Omron CX-Programmer project NuevoProyecto (CX-Programmer 3.01)

# PLC NuevoPLC1: CPM2* 

## Global symbols (name address type ; comment)
DM200 CHANNEL  ; Cantidad de escl
DM201 CHANNEL  ; DM a partir de l
DM2010 CHANNEL  ; CRC del esclavo
DM2011 CHANNEL  ; CRC del esclavo
DM2012 CHANNEL  ; CRC del esclavo
DM2013 CHANNEL  ; CRCdel esclavo 4
DM2014 CHANNEL  ; CRC del esclavo
DM2015 CHANNEL  ; CRC del esclavo
DM2016 CHANNEL  ; CRC del esclavo
DM2017 CHANNEL  ; CRC del esclavo
DM2018 CHANNEL  ; CRC del esclavo
DM2019 CHANNEL  ; CRC del esclavo
DM202 CHANNEL  ; Timeout de cada
DM2020 CHANNEL  ; CRC del esclavo
DM2021 CHANNEL  ; CRC del esclavo
DM2022 CHANNEL  ; CRC del esclavo
DM2023 CHANNEL  ; CRC del esclavo
DM2024 CHANNEL  ; CRC del esclavo
DM2025 CHANNEL  ; CRC del esclavo
DM2026 CHANNEL  ; CRC del esclavo
DM2027 CHANNEL  ; CRC del esclavo
DM2028 CHANNEL  ; CRC del esclavo
DM2029 CHANNEL  ; CRC del esclavo
DM2030 CHANNEL  ; CRC del esclavo
DM2031 CHANNEL  ; CRC del esclavo
DM2032 CHANNEL  ; CRC del esclavo
DM2033 CHANNEL  ; CRC del esclavo
DM2034 CHANNEL  ; CRC del esclavo
DM2035 CHANNEL  ; CRC del esclavo
DM2036 CHANNEL  ; CRC del esclavo
DM2037 CHANNEL  ; CRC del esclavo
DM2038 CHANNEL  ; CRC del esclavo
DM2039 CHANNEL  ; CRC del esclavo
DM2040 CHANNEL  ; CRC del esclavo
DM2041 CHANNEL  ; CRC del esclavo

## Program NuevoPrograma1 (no task)

### Section Sección1

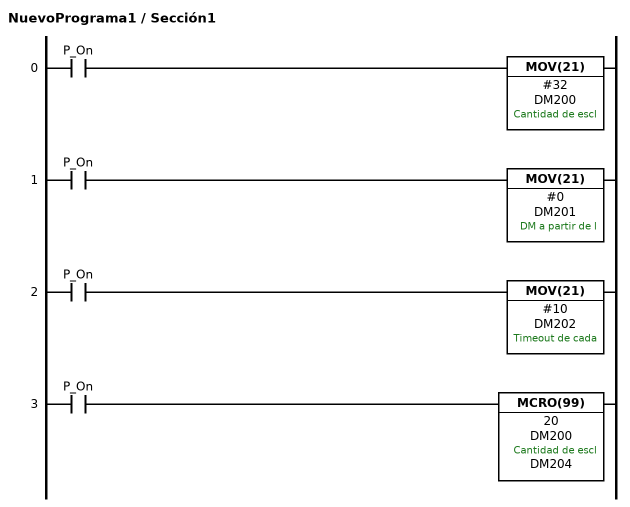
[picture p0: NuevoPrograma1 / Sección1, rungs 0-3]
; rung 0
LD P_On
MOV(21) #32 DM200  ; Cantidad de escl
; rung 1
LD P_On
MOV(21) #0 DM201  ; DM a partir de l
; rung 2
LD P_On
MOV(21) #10 DM202  ; Timeout de cada
; rung 3
LD P_On
MCRO(99) 20 DM200 DM204  ; Cantidad de escl

### Section Sección2

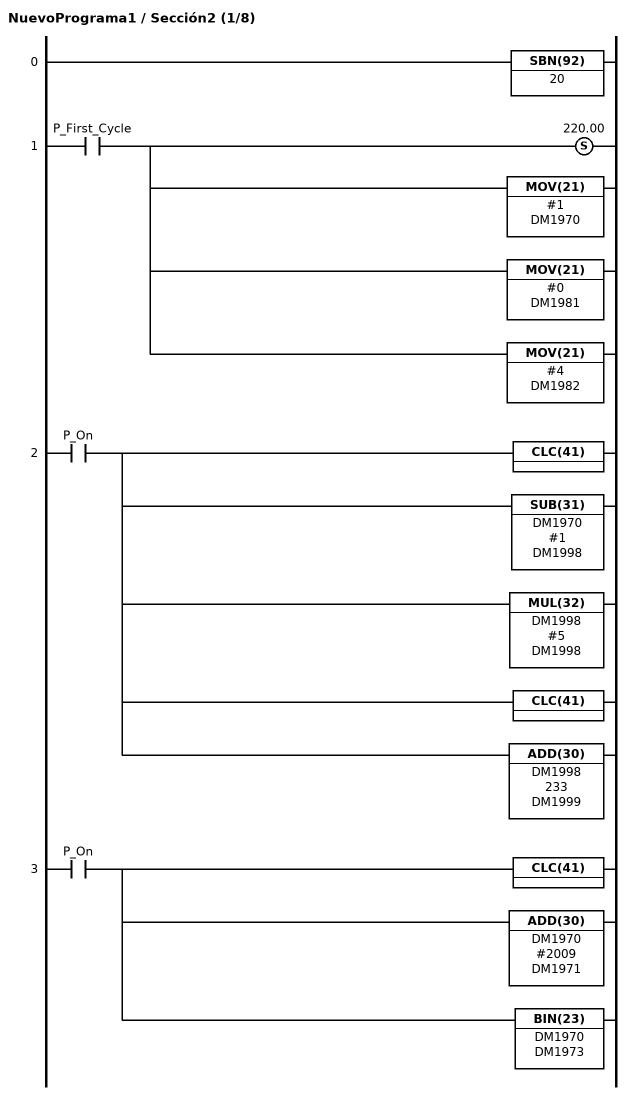
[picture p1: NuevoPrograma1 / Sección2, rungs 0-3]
; rung 0
SBN(92) 20
; rung 1
LD P_First_Cycle
SET 220.00
MOV(21) #1 DM1970
MOV(21) #0 DM1981
MOV(21) #4 DM1982
; rung 2
LD P_On
CLC(41)
SUB(31) DM1970 #1 DM1998
MUL(32) DM1998 #5 DM1998
CLC(41)
ADD(30) DM1998 233 DM1999
; rung 3
LD P_On
CLC(41)
ADD(30) DM1970 #2009 DM1971
BIN(23) DM1970 DM1973

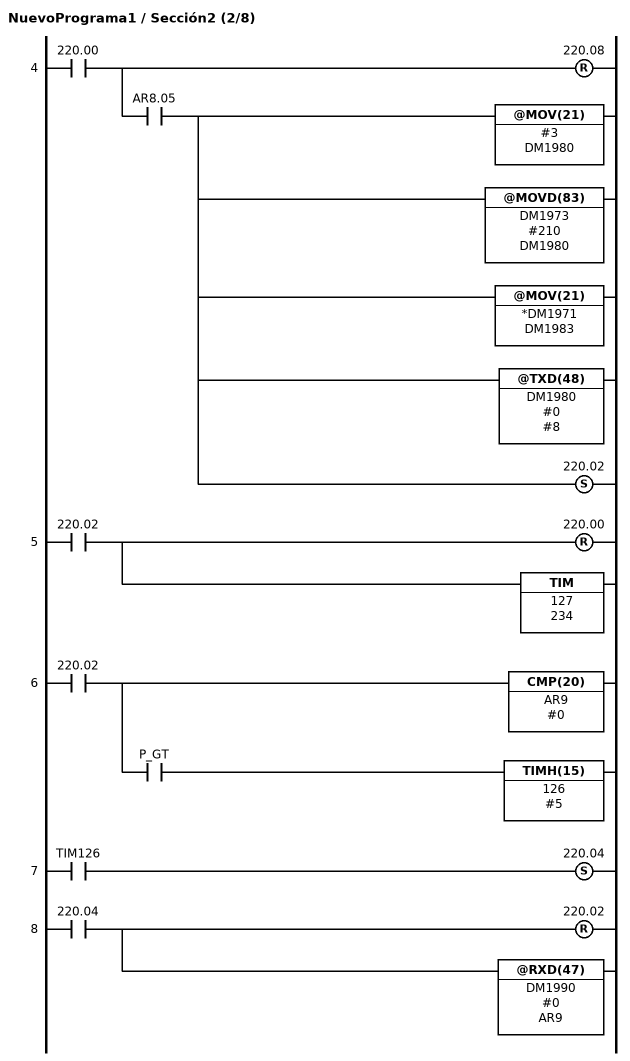
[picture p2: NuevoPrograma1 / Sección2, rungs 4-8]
; rung 4
LD 220.00
RSET 220.08
AND AR8.05
@MOV(21) #3 DM1980
@MOVD(83) DM1973 #210 DM1980
@MOV(21) *DM1971 DM1983
@TXD(48) DM1980 #0 #8
SET 220.02
; rung 5
LD 220.02
RSET 220.00
TIM 127 234
; rung 6
LD 220.02
CMP(20) AR9 #0
AND P_GT
TIMH(15) 126 #5
; rung 7
LD TIM126
SET 220.04
; rung 8
LD 220.04
RSET 220.02
@RXD(47) DM1990 #0 AR9

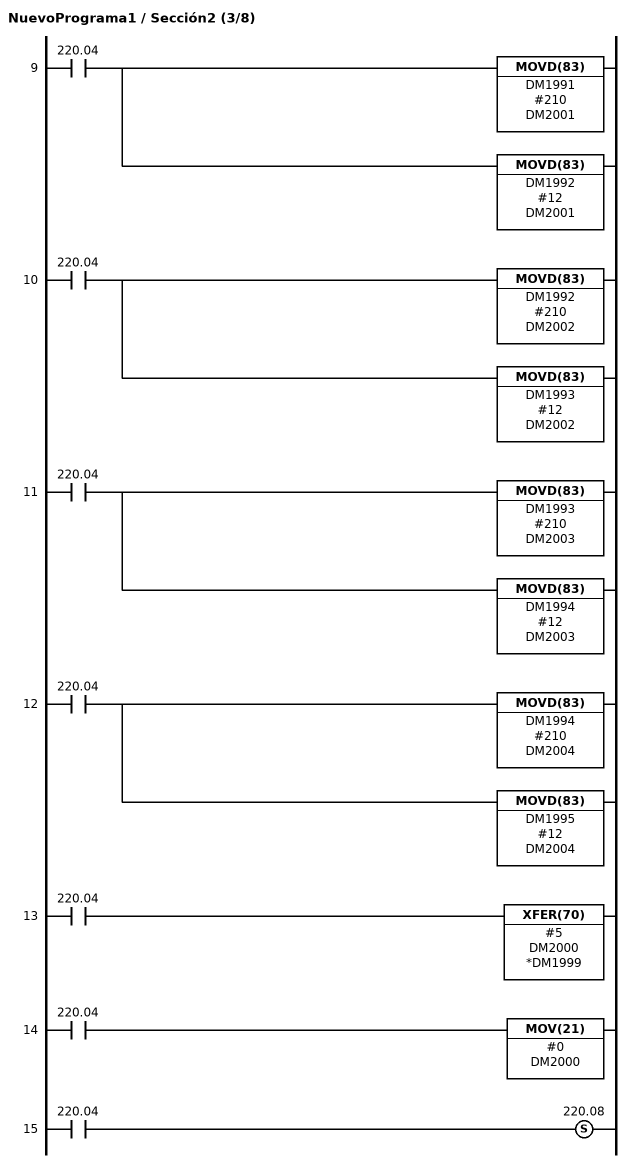
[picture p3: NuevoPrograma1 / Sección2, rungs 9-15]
; rung 9
LD 220.04
MOVD(83) DM1991 #210 DM2001
MOVD(83) DM1992 #12 DM2001
; rung 10
LD 220.04
MOVD(83) DM1992 #210 DM2002
MOVD(83) DM1993 #12 DM2002
; rung 11
LD 220.04
MOVD(83) DM1993 #210 DM2003
MOVD(83) DM1994 #12 DM2003
; rung 12
LD 220.04
MOVD(83) DM1994 #210 DM2004
MOVD(83) DM1995 #12 DM2004
; rung 13
LD 220.04
XFER(70) #5 DM2000 *DM1999
; rung 14
LD 220.04
MOV(21) #0 DM2000
; rung 15
LD 220.04
SET 220.08

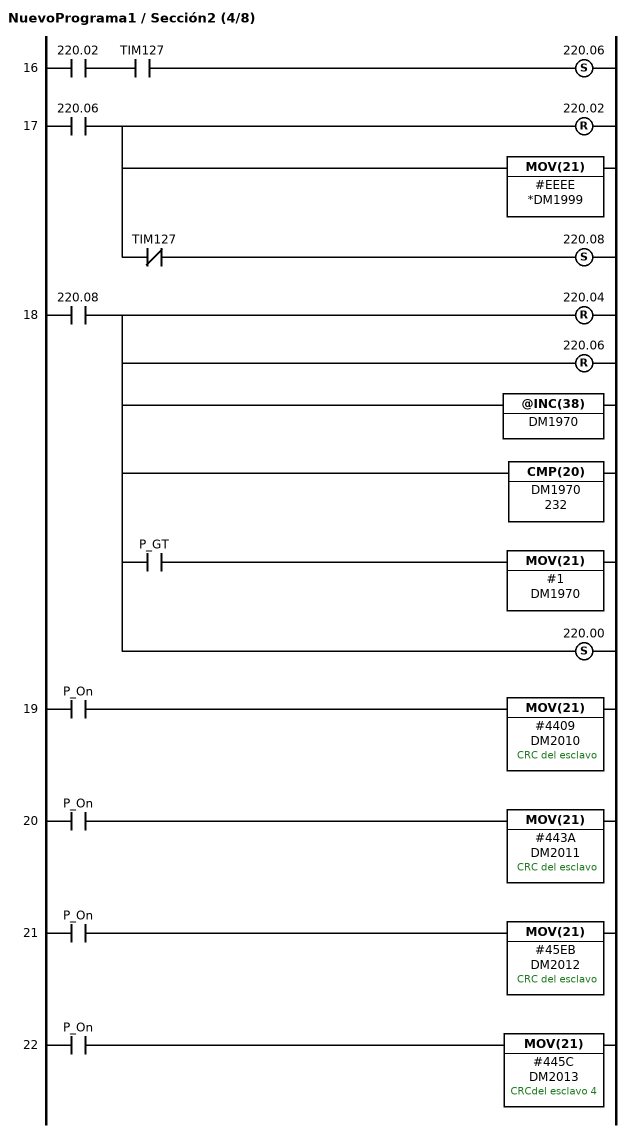
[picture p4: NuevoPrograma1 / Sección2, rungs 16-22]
; rung 16
LD 220.02
AND TIM127
SET 220.06
; rung 17
LD 220.06
RSET 220.02
MOV(21) #EEEE *DM1999
ANDNOT TIM127
SET 220.08
; rung 18
LD 220.08
OUT TR0
RSET 220.04
RSET 220.06
@INC(38) DM1970
CMP(20) DM1970 232
AND P_GT
MOV(21) #1 DM1970
LD TR0
SET 220.00
; rung 19
LD P_On
MOV(21) #4409 DM2010  ; CRC del esclavo
; rung 20
LD P_On
MOV(21) #443A DM2011  ; CRC del esclavo
; rung 21
LD P_On
MOV(21) #45EB DM2012  ; CRC del esclavo
; rung 22
LD P_On
MOV(21) #445C DM2013  ; CRCdel esclavo 4

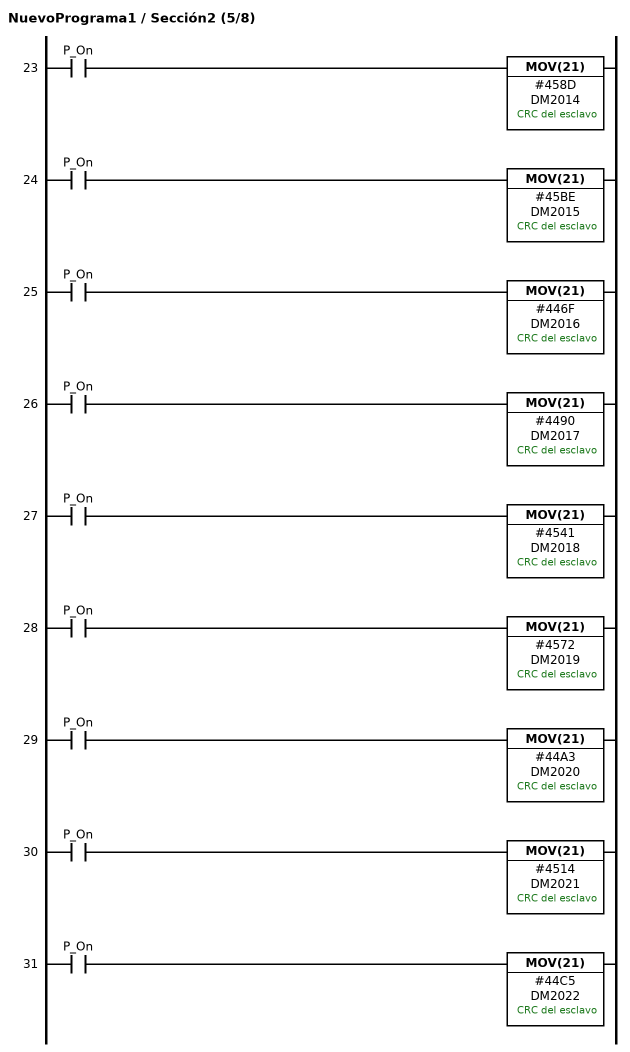
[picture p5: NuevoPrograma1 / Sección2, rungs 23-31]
; rung 23
LD P_On
MOV(21) #458D DM2014  ; CRC del esclavo
; rung 24
LD P_On
MOV(21) #45BE DM2015  ; CRC del esclavo
; rung 25
LD P_On
MOV(21) #446F DM2016  ; CRC del esclavo
; rung 26
LD P_On
MOV(21) #4490 DM2017  ; CRC del esclavo
; rung 27
LD P_On
MOV(21) #4541 DM2018  ; CRC del esclavo
; rung 28
LD P_On
MOV(21) #4572 DM2019  ; CRC del esclavo
; rung 29
LD P_On
MOV(21) #44A3 DM2020  ; CRC del esclavo
; rung 30
LD P_On
MOV(21) #4514 DM2021  ; CRC del esclavo
; rung 31
LD P_On
MOV(21) #44C5 DM2022  ; CRC del esclavo

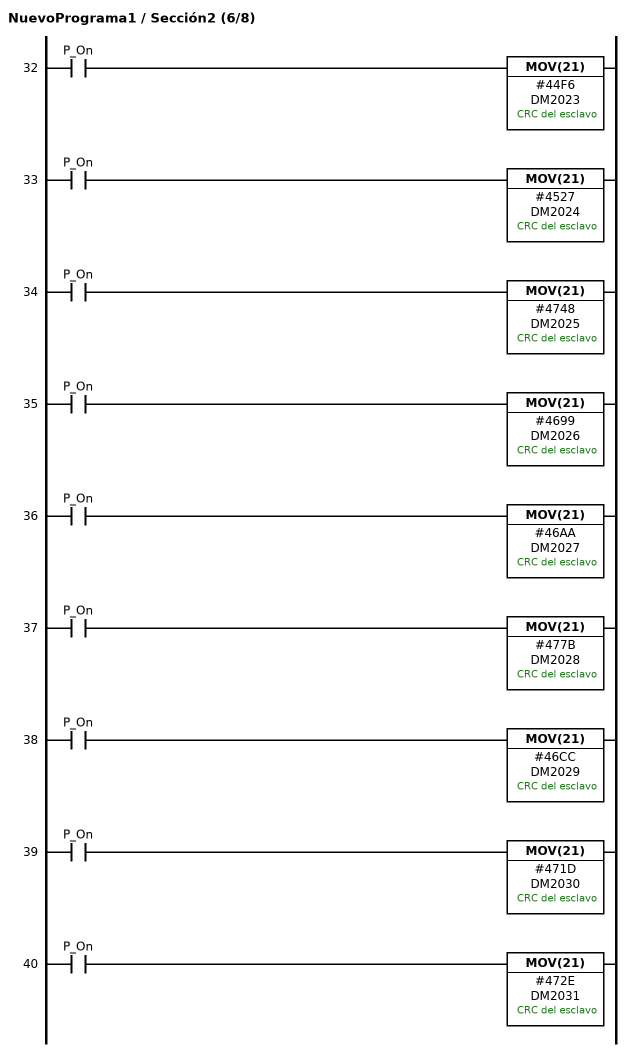
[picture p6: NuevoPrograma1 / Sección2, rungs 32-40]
; rung 32
LD P_On
MOV(21) #44F6 DM2023  ; CRC del esclavo
; rung 33
LD P_On
MOV(21) #4527 DM2024  ; CRC del esclavo
; rung 34
LD P_On
MOV(21) #4748 DM2025  ; CRC del esclavo
; rung 35
LD P_On
MOV(21) #4699 DM2026  ; CRC del esclavo
; rung 36
LD P_On
MOV(21) #46AA DM2027  ; CRC del esclavo
; rung 37
LD P_On
MOV(21) #477B DM2028  ; CRC del esclavo
; rung 38
LD P_On
MOV(21) #46CC DM2029  ; CRC del esclavo
; rung 39
LD P_On
MOV(21) #471D DM2030  ; CRC del esclavo
; rung 40
LD P_On
MOV(21) #472E DM2031  ; CRC del esclavo

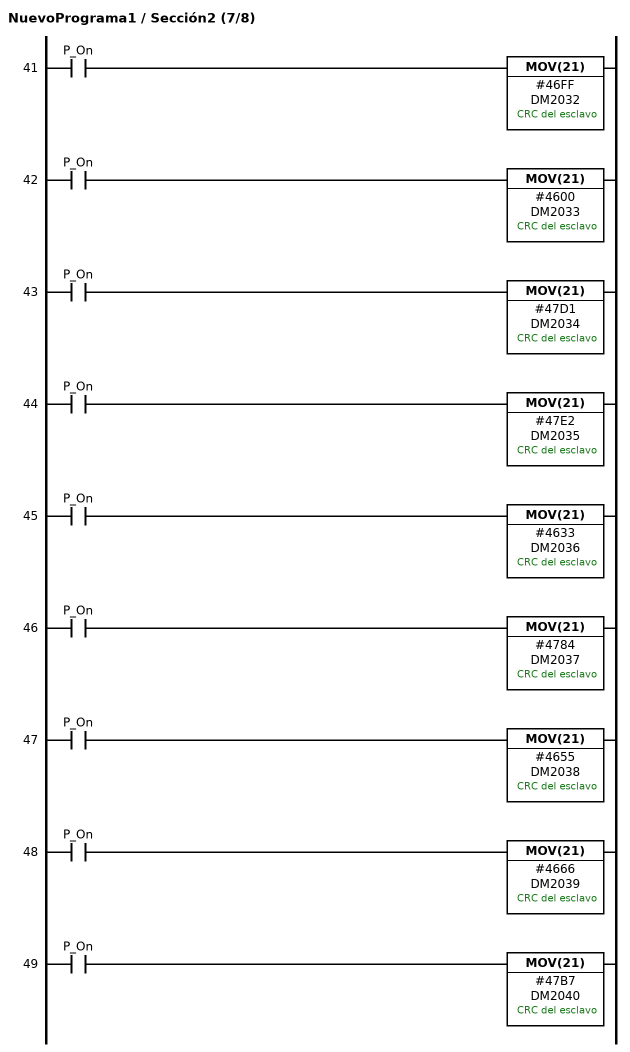
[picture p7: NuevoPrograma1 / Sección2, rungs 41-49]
; rung 41
LD P_On
MOV(21) #46FF DM2032  ; CRC del esclavo
; rung 42
LD P_On
MOV(21) #4600 DM2033  ; CRC del esclavo
; rung 43
LD P_On
MOV(21) #47D1 DM2034  ; CRC del esclavo
; rung 44
LD P_On
MOV(21) #47E2 DM2035  ; CRC del esclavo
; rung 45
LD P_On
MOV(21) #4633 DM2036  ; CRC del esclavo
; rung 46
LD P_On
MOV(21) #4784 DM2037  ; CRC del esclavo
; rung 47
LD P_On
MOV(21) #4655 DM2038  ; CRC del esclavo
; rung 48
LD P_On
MOV(21) #4666 DM2039  ; CRC del esclavo
; rung 49
LD P_On
MOV(21) #47B7 DM2040  ; CRC del esclavo

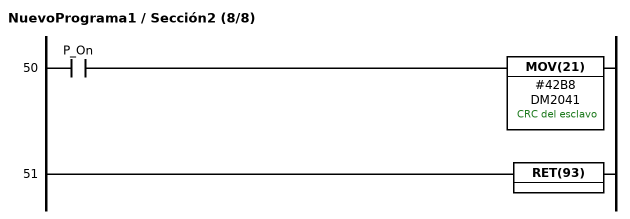
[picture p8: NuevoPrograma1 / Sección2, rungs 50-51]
; rung 50
LD P_On
MOV(21) #42B8 DM2041  ; CRC del esclavo
; rung 51
RET(93)

### Section Sección3
; rung 0
END(01)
